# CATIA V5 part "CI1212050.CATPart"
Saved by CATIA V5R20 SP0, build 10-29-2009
Part number: CI1212050
Bounding box of the stored display mesh (mm): x -12 to 12, y -10.22 to 68, z -13.659 to 13.975
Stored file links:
  C:\Users\Raffaele\Desktop\3D X SITO CF\BOLEX\19-INCLINED ASSEMBLY REF_CI\CI1212050.CATPart
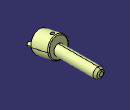
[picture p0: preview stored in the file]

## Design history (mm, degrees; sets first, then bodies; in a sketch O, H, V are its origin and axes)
Set1
  DatumSurface1 to DatumSurface16 "MANIFOLD_SOLID_BREP #377"
  DatumSurface17 to DatumSurface39 "MANIFOLD_SOLID_BREP #1094"
Body1 (main body)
